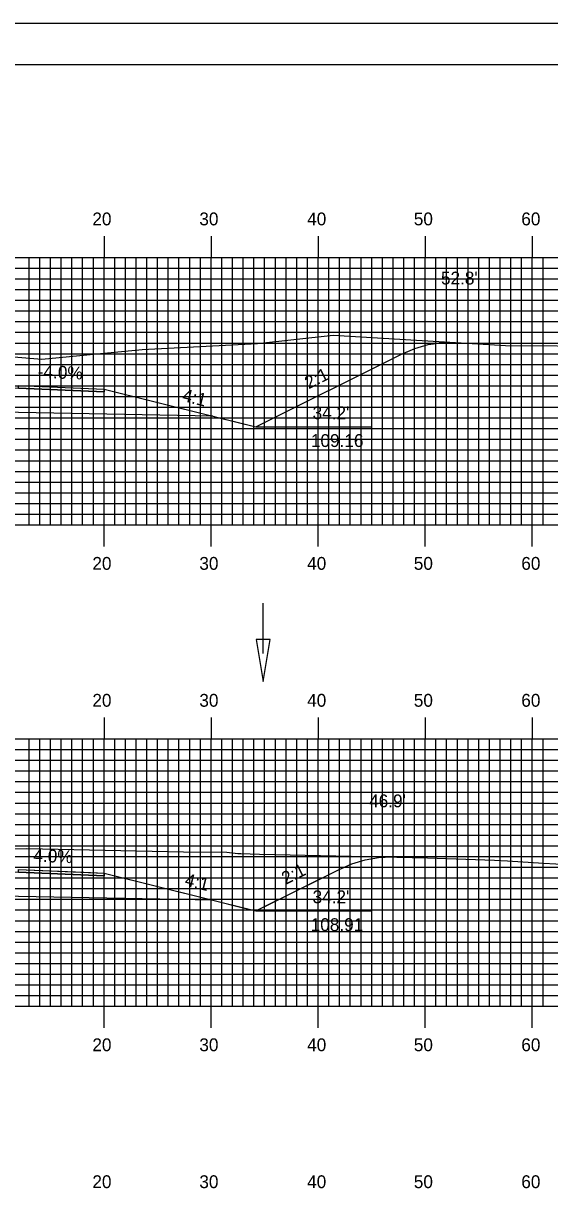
# Model space of a CAD drawing. Extents: x 1766513 to 1766856, y 442591 to 442811.
# Drawn here: x 1766691.4 to 1766740.5, y 442701.2 to 442810.5 of the extents above; entities that cross this region are included whole.
import ezdxf

# ---------------------------------------------------------------- set-up
doc = ezdxf.new("R2010")
doc.units = 0
for name, color, linetype in [('ANNOTATION', 7, 'Continuous'), ('BORDER', 7, 'Continuous'), ('D_Drainage_Ditch_Line', 7, 'Continuous'), ('D_Roadway_Centerline', 7, 'Continuous'), ('D_Roadway_Edge_Shoulder', 7, 'Continuous'), ('D_Roadway_SlopeLines', 7, 'Continuous'), ('D_Roadway_SubGrade', 7, 'Continuous'), ('D_Text_Standard', 7, 'Continuous'), ('H_V ANNOTATION', 7, 'Continuous'), ('MAJOR', 7, 'Continuous'), ('MINOR', 7, 'Continuous'), ('PDRAIN', 7, 'Continuous'), ('PLOT BOUNDARY', 7, 'Continuous'), ('S_Roadway_Centerline', 7, 'Continuous')]:
    doc.layers.add(name, color=color, linetype=linetype)

msp = doc.modelspace()

# ---------------------------------------------------------------- linework, layer by layer
at = {"layer": 'BORDER'}
msp.add_lwpolyline([(1766529.31, 442596.67), (1766849.31, 442596.67), (1766849.31, 442806.67), (1766529.31, 442806.67)], close=True, dxfattribs=at)
at = {"layer": 'D_Drainage_Ditch_Line'}
msp.add_line((1766713.77, 442751.66), (1766713.77, 442756.36), dxfattribs=at)
msp.add_lwpolyline([(1766714.43, 442752.97), (1766713.12, 442752.97), (1766713.77, 442749.03)], close=True, dxfattribs=at)
at = {"layer": 'D_Roadway_Centerline'}
for points in [[(1766690.91, 442776.69), (1766698.91, 442776.37), (1766709.08, 442773.83), (1766709.42, 442773.74), (1766713.08, 442772.83), (1766726.68, 442779.63), (1766727.88, 442780.14), (1766727.93, 442780.17), (1766729.18, 442780.53), (1766729.68, 442780.6), (1766730.43, 442780.72), (1766731.68, 442780.73)], [(1766690.91, 442731.44), (1766697.03, 442731.2), (1766698.91, 442731.12), (1766709.08, 442728.58), (1766709.08, 442728.58), (1766711.79, 442727.9), (1766713.08, 442727.58), (1766714.66, 442728.37), (1766720.8, 442731.43), (1766722.05, 442731.98), (1766723.3, 442732.36), (1766724.55, 442732.58), (1766725.8, 442732.63)]]:
    msp.add_lwpolyline(points, dxfattribs=at)
at = {"layer": 'D_Roadway_Edge_Shoulder'}
for points in [[(1766690.91, 442776.69), (1766698.91, 442776.37), (1766698.91, 442776.12), (1766690.91, 442776.44)], [(1766690.91, 442731.44), (1766698.91, 442731.12), (1766698.91, 442730.87), (1766690.91, 442731.19)]]:
    msp.add_lwpolyline(points, close=True, dxfattribs=at)
at = {"layer": 'D_Roadway_SlopeLines'}
for points in [[(1766713.08, 442772.83), (1766726.68, 442779.63), (1766727.93, 442780.17), (1766729.18, 442780.53), (1766730.43, 442780.72), (1766731.68, 442780.73)], [(1766698.91, 442776.37), (1766713.08, 442772.83)], [(1766713.08, 442727.58), (1766720.8, 442731.43), (1766722.05, 442731.98), (1766723.29, 442732.36), (1766724.55, 442732.58), (1766725.8, 442732.63)], [(1766698.91, 442731.12), (1766713.08, 442727.58)]]:
    msp.add_lwpolyline(points, dxfattribs=at)
at = {"layer": 'D_Roadway_SubGrade'}
for points in [[(1766666.91, 442774.72), (1766648.74, 442774.36), (1766658.91, 442776.9), (1766658.91, 442776.65), (1766666.91, 442776.97), (1766678.91, 442776.71), (1766690.91, 442776.44), (1766698.91, 442776.12), (1766698.91, 442776.37), (1766709.08, 442773.83), (1766690.91, 442774.19), (1766678.91, 442774.46)], [(1766666.91, 442729.47), (1766648.74, 442729.11), (1766658.91, 442731.65), (1766658.91, 442731.4), (1766666.91, 442731.72), (1766678.91, 442731.46), (1766690.91, 442731.19), (1766698.91, 442730.87), (1766698.91, 442731.12), (1766709.08, 442728.58), (1766690.91, 442728.94), (1766678.91, 442729.21)]]:
    msp.add_lwpolyline(points, close=True, dxfattribs=at)
at = {"layer": 'MAJOR'}
for p, q in [((1766698.91, 442790.67), (1766698.91, 442788.67)), ((1766708.91, 442790.67), (1766708.91, 442788.67)), ((1766718.91, 442790.67), (1766718.91, 442788.67)), ((1766728.91, 442790.67), (1766728.91, 442788.67)), ((1766738.91, 442790.67), (1766738.91, 442788.67)), ((1766538.91, 442788.67), (1766818.91, 442788.67)), ((1766538.91, 442788.67), (1766818.91, 442788.67)), ((1766698.91, 442763.67), (1766698.91, 442788.67)), ((1766708.91, 442763.67), (1766708.91, 442788.67)), ((1766718.91, 442763.67), (1766718.91, 442788.67)), ((1766728.91, 442763.67), (1766728.91, 442788.67)), ((1766738.91, 442763.67), (1766738.91, 442788.67)), ((1766538.91, 442783.67), (1766818.91, 442783.67)), ((1766538.91, 442778.67), (1766818.91, 442778.67)), ((1766538.91, 442773.67), (1766818.91, 442773.67)), ((1766538.91, 442768.67), (1766818.91, 442768.67)), ((1766538.91, 442763.67), (1766818.91, 442763.67)), ((1766538.91, 442763.67), (1766818.91, 442763.67)), ((1766698.91, 442761.66), (1766698.91, 442763.67)), ((1766708.91, 442761.66), (1766708.91, 442763.67)), ((1766718.91, 442761.66), (1766718.91, 442763.67)), ((1766728.91, 442761.66), (1766728.91, 442763.67)), ((1766738.91, 442761.66), (1766738.91, 442763.67)), ((1766698.91, 442745.67), (1766698.91, 442743.67)), ((1766708.91, 442745.67), (1766708.91, 442743.67)), ((1766718.91, 442745.67), (1766718.91, 442743.67)), ((1766728.91, 442745.67), (1766728.91, 442743.67)), ((1766738.91, 442745.67), (1766738.91, 442743.67)), ((1766538.91, 442743.67), (1766818.91, 442743.67)), ((1766538.91, 442743.67), (1766818.91, 442743.67)), ((1766698.91, 442718.67), (1766698.91, 442743.67)), ((1766708.91, 442718.67), (1766708.91, 442743.67)), ((1766718.91, 442718.67), (1766718.91, 442743.67)), ((1766728.91, 442718.67), (1766728.91, 442743.67)), ((1766738.91, 442718.67), (1766738.91, 442743.67)), ((1766538.91, 442738.67), (1766818.91, 442738.67)), ((1766538.91, 442733.67), (1766818.91, 442733.67)), ((1766538.91, 442728.67), (1766818.91, 442728.67)), ((1766538.91, 442723.67), (1766818.91, 442723.67)), ((1766538.91, 442718.67), (1766818.91, 442718.67)), ((1766538.91, 442718.67), (1766818.91, 442718.67)), ((1766698.91, 442716.66), (1766698.91, 442718.67)), ((1766708.91, 442716.66), (1766708.91, 442718.67)), ((1766718.91, 442716.66), (1766718.91, 442718.67)), ((1766728.91, 442716.66), (1766728.91, 442718.67)), ((1766738.91, 442716.66), (1766738.91, 442718.67))]:
    msp.add_line(p, q, dxfattribs=at)
at = {"layer": 'MINOR'}
for p, q in [((1766691.91, 442763.67), (1766691.91, 442788.67)), ((1766692.91, 442763.67), (1766692.91, 442788.67)), ((1766693.91, 442763.67), (1766693.91, 442788.67)), ((1766694.91, 442763.67), (1766694.91, 442788.67)), ((1766695.91, 442763.67), (1766695.91, 442788.67)), ((1766696.91, 442763.67), (1766696.91, 442788.67)), ((1766697.91, 442763.67), (1766697.91, 442788.67)), ((1766699.91, 442763.67), (1766699.91, 442788.67)), ((1766700.91, 442763.67), (1766700.91, 442788.67)), ((1766701.91, 442763.67), (1766701.91, 442788.67)), ((1766702.91, 442763.67), (1766702.91, 442788.67)), ((1766703.91, 442763.67), (1766703.91, 442788.67)), ((1766704.91, 442763.67), (1766704.91, 442788.67)), ((1766705.91, 442763.67), (1766705.91, 442788.67)), ((1766706.91, 442763.67), (1766706.91, 442788.67)), ((1766707.91, 442763.67), (1766707.91, 442788.67)), ((1766709.91, 442763.67), (1766709.91, 442788.67)), ((1766710.91, 442763.67), (1766710.91, 442788.67)), ((1766711.91, 442763.67), (1766711.91, 442788.67)), ((1766712.91, 442763.67), (1766712.91, 442788.67)), ((1766713.91, 442763.67), (1766713.91, 442788.67)), ((1766714.91, 442763.67), (1766714.91, 442788.67)), ((1766715.91, 442763.67), (1766715.91, 442788.67)), ((1766716.91, 442763.67), (1766716.91, 442788.67)), ((1766717.91, 442763.67), (1766717.91, 442788.67)), ((1766719.91, 442763.67), (1766719.91, 442788.67)), ((1766720.91, 442763.67), (1766720.91, 442788.67)), ((1766721.91, 442763.67), (1766721.91, 442788.67)), ((1766722.91, 442763.67), (1766722.91, 442788.67)), ((1766723.91, 442763.67), (1766723.91, 442788.67)), ((1766724.91, 442763.67), (1766724.91, 442788.67)), ((1766725.91, 442763.67), (1766725.91, 442788.67)), ((1766726.91, 442763.67), (1766726.91, 442788.67)), ((1766727.91, 442763.67), (1766727.91, 442788.67)), ((1766729.91, 442763.67), (1766729.91, 442788.67)), ((1766730.91, 442763.67), (1766730.91, 442788.67)), ((1766731.91, 442763.67), (1766731.91, 442788.67)), ((1766732.91, 442763.67), (1766732.91, 442788.67)), ((1766733.91, 442763.67), (1766733.91, 442788.67)), ((1766734.91, 442763.67), (1766734.91, 442788.67)), ((1766735.91, 442763.67), (1766735.91, 442788.67)), ((1766736.91, 442763.67), (1766736.91, 442788.67)), ((1766737.91, 442763.67), (1766737.91, 442788.67)), ((1766739.91, 442763.67), (1766739.91, 442788.67)), ((1766538.91, 442787.67), (1766818.91, 442787.67)), ((1766538.91, 442786.67), (1766818.91, 442786.67)), ((1766538.91, 442785.67), (1766818.91, 442785.67)), ((1766538.91, 442784.67), (1766818.91, 442784.67)), ((1766538.91, 442782.67), (1766818.91, 442782.67)), ((1766538.91, 442781.67), (1766818.91, 442781.67)), ((1766538.91, 442780.67), (1766818.91, 442780.67)), ((1766538.91, 442779.67), (1766818.91, 442779.67)), ((1766538.91, 442777.67), (1766818.91, 442777.67)), ((1766538.91, 442776.67), (1766818.91, 442776.67)), ((1766538.91, 442775.67), (1766818.91, 442775.67)), ((1766538.91, 442774.67), (1766818.91, 442774.67)), ((1766538.91, 442772.67), (1766818.91, 442772.67)), ((1766538.91, 442771.67), (1766818.91, 442771.67)), ((1766538.91, 442770.67), (1766818.91, 442770.67)), ((1766538.91, 442769.67), (1766818.91, 442769.67)), ((1766538.91, 442767.67), (1766818.91, 442767.67)), ((1766538.91, 442766.67), (1766818.91, 442766.67)), ((1766538.91, 442765.67), (1766818.91, 442765.67)), ((1766538.91, 442764.67), (1766818.91, 442764.67)), ((1766691.91, 442718.67), (1766691.91, 442743.67)), ((1766692.91, 442718.67), (1766692.91, 442743.67)), ((1766693.91, 442718.67), (1766693.91, 442743.67)), ((1766694.91, 442718.67), (1766694.91, 442743.67)), ((1766695.91, 442718.67), (1766695.91, 442743.67)), ((1766696.91, 442718.67), (1766696.91, 442743.67)), ((1766697.91, 442718.67), (1766697.91, 442743.67)), ((1766699.91, 442718.67), (1766699.91, 442743.67)), ((1766700.91, 442718.67), (1766700.91, 442743.67)), ((1766701.91, 442718.67), (1766701.91, 442743.67)), ((1766702.91, 442718.67), (1766702.91, 442743.67)), ((1766703.91, 442718.67), (1766703.91, 442743.67)), ((1766704.91, 442718.67), (1766704.91, 442743.67)), ((1766705.91, 442718.67), (1766705.91, 442743.67)), ((1766706.91, 442718.67), (1766706.91, 442743.67)), ((1766707.91, 442718.67), (1766707.91, 442743.67)), ((1766709.91, 442718.67), (1766709.91, 442743.67)), ((1766710.91, 442718.67), (1766710.91, 442743.67)), ((1766711.91, 442718.67), (1766711.91, 442743.67)), ((1766712.91, 442718.67), (1766712.91, 442743.67)), ((1766713.91, 442718.67), (1766713.91, 442743.67)), ((1766714.91, 442718.67), (1766714.91, 442743.67)), ((1766715.91, 442718.67), (1766715.91, 442743.67)), ((1766716.91, 442718.67), (1766716.91, 442743.67)), ((1766717.91, 442718.67), (1766717.91, 442743.67)), ((1766719.91, 442718.67), (1766719.91, 442743.67)), ((1766720.91, 442718.67), (1766720.91, 442743.67)), ((1766721.91, 442718.67), (1766721.91, 442743.67)), ((1766722.91, 442718.67), (1766722.91, 442743.67)), ((1766723.91, 442718.67), (1766723.91, 442743.67)), ((1766724.91, 442718.67), (1766724.91, 442743.67)), ((1766725.91, 442718.67), (1766725.91, 442743.67)), ((1766726.91, 442718.67), (1766726.91, 442743.67)), ((1766727.91, 442718.67), (1766727.91, 442743.67)), ((1766729.91, 442718.67), (1766729.91, 442743.67)), ((1766730.91, 442718.67), (1766730.91, 442743.67)), ((1766731.91, 442718.67), (1766731.91, 442743.67)), ((1766732.91, 442718.67), (1766732.91, 442743.67)), ((1766733.91, 442718.67), (1766733.91, 442743.67)), ((1766734.91, 442718.67), (1766734.91, 442743.67)), ((1766735.91, 442718.67), (1766735.91, 442743.67)), ((1766736.91, 442718.67), (1766736.91, 442743.67)), ((1766737.91, 442718.67), (1766737.91, 442743.67)), ((1766739.91, 442718.67), (1766739.91, 442743.67)), ((1766538.91, 442742.67), (1766818.91, 442742.67)), ((1766538.91, 442741.67), (1766818.91, 442741.67)), ((1766538.91, 442740.67), (1766818.91, 442740.67)), ((1766538.91, 442739.67), (1766818.91, 442739.67)), ((1766538.91, 442737.67), (1766818.91, 442737.67)), ((1766538.91, 442736.67), (1766818.91, 442736.67)), ((1766538.91, 442735.67), (1766818.91, 442735.67)), ((1766538.91, 442734.67), (1766818.91, 442734.67)), ((1766538.91, 442732.67), (1766818.91, 442732.67)), ((1766538.91, 442731.67), (1766818.91, 442731.67)), ((1766538.91, 442730.67), (1766818.91, 442730.67)), ((1766538.91, 442729.67), (1766818.91, 442729.67)), ((1766538.91, 442727.67), (1766818.91, 442727.67)), ((1766538.91, 442726.67), (1766818.91, 442726.67)), ((1766538.91, 442725.67), (1766818.91, 442725.67)), ((1766538.91, 442724.67), (1766818.91, 442724.67)), ((1766538.91, 442722.67), (1766818.91, 442722.67)), ((1766538.91, 442721.67), (1766818.91, 442721.67)), ((1766538.91, 442720.67), (1766818.91, 442720.67)), ((1766538.91, 442719.67), (1766818.91, 442719.67))]:
    msp.add_line(p, q, dxfattribs=at)
at = {"layer": 'PDRAIN'}
for p, q in [((1766713.08, 442772.83), (1766723.85, 442772.83)), ((1766713.08, 442727.58), (1766723.86, 442727.58))]:
    msp.add_line(p, q, dxfattribs=at)
at = {"layer": 'PLOT BOUNDARY'}
msp.add_lwpolyline([(1766513.12, 442590.55), (1766853.12, 442590.55), (1766853.12, 442810.55), (1766513.12, 442810.55)], close=True, dxfattribs=at)
at = {"layer": 'S_Roadway_Centerline'}
for points in [[(1766624.73, 442778.8), (1766626.23, 442778.81), (1766626.78, 442778.79), (1766632.27, 442779.76), (1766640.92, 442779.99), (1766641.66, 442779.96), (1766648.07, 442780.08), (1766649.09, 442780.11), (1766650.89, 442780.16), (1766651.15, 442780.15), (1766651.23, 442780.15), (1766652.03, 442780.27), (1766663.75, 442778.16), (1766668.13, 442778.55), (1766674.3, 442779.41), (1766677.38, 442779.78), (1766681.1, 442780.16), (1766693.09, 442779.16), (1766702.46, 442780.05), (1766713.25, 442780.62), (1766720.31, 442781.41), (1766736.42, 442780.44), (1766746.09, 442780.38)], [(1766616.64, 442734.31), (1766626.82, 442733.97), (1766643.96, 442732.59), (1766646.35, 442732.5), (1766646.57, 442732.41), (1766649.33, 442732.56), (1766655.29, 442732.91), (1766658.44, 442733.09), (1766661.35, 442733.08), (1766672.82, 442733.06), (1766675.13, 442733.03), (1766679.72, 442733.11), (1766687.81, 442733.33), (1766691.7, 442733.42), (1766706.32, 442733.12), (1766710.37, 442733.06), (1766711.41, 442732.95), (1766711.68, 442732.95), (1766713.44, 442732.89), (1766729.11, 442732.56), (1766735.39, 442732.32), (1766736.6, 442732.25), (1766739.94, 442732.05), (1766742.27, 442731.91)]]:
    msp.add_lwpolyline(points, dxfattribs=at)

# ---------------------------------------------------------------- texts
at = {"layer": 'ANNOTATION'}
for s, rotation, p in [('-4.0%', 357.7093, (1766692.7, 442777.42)), ('2:1', 26.5646, (1766718.03, 442776.34)), ('4:1', 345.962, (1766706.14, 442775.26)), ('-4.0%', 357.7095, (1766691.76, 442732.21)), ('2:1', 26.5674, (1766715.87, 442730.01)), ('4:1', 345.9608, (1766706.38, 442729.97))]:
    msp.add_text(s, height=1.2, rotation=rotation, dxfattribs=at).set_placement(p)
for s, p in [("34.2'", (1766718.39, 442773.55)), ('109.16', (1766718.23, 442770.95)), ("34.2'", (1766718.39, 442728.3)), ('108.91', (1766718.21, 442725.7))]:
    msp.add_text(s, height=1.2, dxfattribs=at).set_placement(p)
at = {"layer": 'D_Text_Standard'}
for s, p in [("52.8'", (1766730.38, 442786.14)), ("46.9'", (1766723.67, 442737.27))]:
    msp.add_text(s, height=1.2, dxfattribs=at).set_placement(p)
at = {"layer": 'H_V ANNOTATION'}
for s, p in [('20', (1766697.82, 442791.67)), ('30', (1766707.81, 442791.67)), ('40', (1766717.88, 442791.67)), ('50', (1766727.84, 442791.67)), ('60', (1766737.88, 442791.67)), ('20', (1766697.82, 442759.47)), ('30', (1766707.81, 442759.47)), ('40', (1766717.88, 442759.47)), ('50', (1766727.84, 442759.47)), ('60', (1766737.88, 442759.47)), ('20', (1766697.82, 442746.67)), ('30', (1766707.81, 442746.67)), ('40', (1766717.88, 442746.67)), ('50', (1766727.84, 442746.67)), ('60', (1766737.88, 442746.67)), ('20', (1766697.82, 442714.47)), ('30', (1766707.81, 442714.47)), ('40', (1766717.88, 442714.47)), ('50', (1766727.84, 442714.47)), ('60', (1766737.88, 442714.47)), ('20', (1766697.82, 442701.67)), ('30', (1766707.81, 442701.67)), ('40', (1766717.88, 442701.67)), ('50', (1766727.84, 442701.67)), ('60', (1766737.88, 442701.67))]:
    msp.add_text(s, height=1.2, dxfattribs=at).set_placement(p)

doc.saveas('drawing.dxf')
